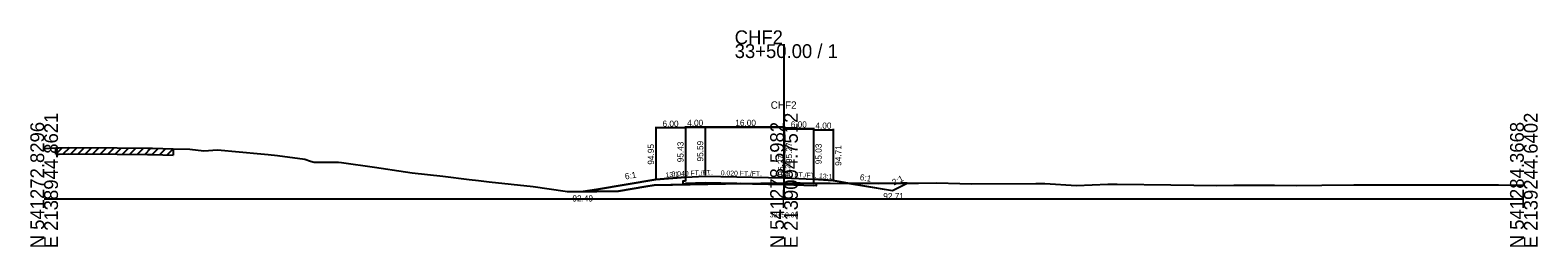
# Model space of a CAD drawing. Extents: x -12831 to 2303, y -10 to 39065.
# Drawn here: x 997.2 to 1302.8, y 6990.3 to 7034.2 of the extents above; entities that cross this region are included whole.
import ezdxf

# ---------------------------------------------------------------- set-up
doc = ezdxf.new("R2010")
doc.units = 0
for name, color, linetype in [('Level 5', 7, 'Continuous'), ('Level 53', 7, 'Continuous'), ('Level 54', 7, 'Continuous'), ('Level 55', 7, 'Continuous'), ('Level 7', 7, 'Continuous'), ('RD_GPK_XS_Cell', 7, 'Continuous'), ('RD_XS_EwShp', 7, 'Continuous'), ('RD_XS_ExGround', 7, 'Continuous'), ('RD_XS_ExPaveRet', 7, 'Continuous'), ('RD_XS_Pave', 7, 'Continuous'), ('RD_XS_TX_Baseline', 7, 'Continuous'), ('RD_XS_TX_Elev_EX', 7, 'Continuous'), ('RD_XS_TX_Elev_PR', 7, 'Continuous'), ('RD_XS_TX_Station', 7, 'Continuous')]:
    doc.layers.add(name, color=color, linetype=linetype)

msp = doc.modelspace()

# ---------------------------------------------------------------- linework, layer by layer
at = {"layer": 'Level 5'}
for p, q in [((1130, 7003.6), (1129.5, 7003.58)), ((1129.5, 7003.58), (1129.5, 7003.08)), ((1130, 7004.43), (1130, 7003.6)), ((1134, 7003.26), (1130, 7003.1)), ((1134, 7003.26), (1130, 7003.1)), ((1130, 7003.1), (1134, 7003.26)), ((1150, 7002.94), (1134, 7003.26)), ((1150, 7002.94), (1134, 7003.26)), ((1134, 7003.26), (1150, 7002.94)), ((1134, 7003.26), (1150, 7002.94)), ((1156, 7004.03), (1156, 7003.2)), ((1156, 7003.2), (1156.5, 7003.18)), ((1156.5, 7003.18), (1156.5, 7002.68)), ((1129.5, 7003.08), (1130, 7003.1)), ((1156, 7002.7), (1150, 7002.94)), ((1150, 7002.94), (1156, 7002.7)), ((1150, 7002.94), (1156, 7002.7)), ((1156.5, 7002.68), (1156, 7002.7))]:
    msp.add_line(p, q, dxfattribs=at)
at = {"layer": 'Level 54'}
for p, q in [((1124, 7014.58), (1124, 7004.15)), ((1130, 7014.38), (1124, 7014.38)), ((1130, 7014.74), (1130, 7004.63)), ((1130, 7014.74), (1130, 7004.63)), ((1130, 7014.74), (1130, 7004.63)), ((1130, 7014.58), (1130, 7004.63)), ((1130, 7014.54), (1134, 7014.54)), ((1130, 7014.54), (1134, 7014.54)), ((1134, 7014.54), (1130, 7014.54)), ((1134, 7014.74), (1134, 7004.79)), ((1134, 7014.74), (1134, 7004.79)), ((1134, 7014.74), (1134, 7004.79)), ((1134, 7014.74), (1134, 7004.79)), ((1134, 7014.74), (1134, 7004.79)), ((1134, 7014.74), (1134, 7004.79)), ((1134, 7014.74), (1134, 7004.79)), ((1134, 7014.54), (1150, 7014.54)), ((1134, 7014.54), (1150, 7014.54)), ((1150, 7014.54), (1134, 7014.54)), ((1150, 7014.54), (1134, 7014.54)), ((1150, 7014.74), (1150, 7004.47)), ((1150, 7014.74), (1150, 7004.47)), ((1150, 7014.74), (1150, 7004.47)), ((1150, 7014.74), (1150, 7004.47)), ((1150, 7014.42), (1150, 7004.47)), ((1150, 7014.42), (1150, 7004.47)), ((1150, 7014.42), (1150, 7004.47)), ((1150, 7014.22), (1156, 7014.22)), ((1156, 7014.22), (1150, 7014.22)), ((1156, 7014.22), (1150, 7014.22)), ((1156, 7014.42), (1156, 7004.23)), ((1156, 7014.42), (1156, 7004.23)), ((1156, 7014.42), (1156, 7004.23)), ((1156, 7014.18), (1156, 7004.23)), ((1156, 7013.98), (1160, 7013.98)), ((1160, 7014.18), (1160, 7003.91))]:
    msp.add_line(p, q, dxfattribs=at)
at = {"layer": 'Level 7'}
for p, q in [((1124, 7003.95), (1112, 7001.95)), ((1130, 7004.43), (1124, 7003.95)), ((1156, 7004.03), (1160, 7003.71)), ((1160, 7003.71), (1172, 7001.71)), ((1172, 7001.71), (1174.94, 7003.18)), ((1112, 7001.95), (1109.25, 7001.49))]:
    msp.add_line(p, q, dxfattribs=at)
at = {"layer": 'RD_GPK_XS_Cell'}
for p, q in [((1150, 7000), (1150, 7031.35)), ((1000, 7000), (1150, 7000)), ((1150, 7000), (1300, 7000))]:
    msp.add_line(p, q, dxfattribs=at)
at = {"layer": 'RD_XS_EwShp'}
for points in [[(1130, 7003.6), (1129.5, 7003.58), (1129.5, 7003.08), (1130, 7003.1), (1134, 7003.26), (1141.25, 7003.11), (1127.38, 7002.88), (1127.06, 7002.88), (1123.69, 7002.78), (1121.96, 7002.52), (1116.45, 7001.6), (1112.06, 7001.48), (1109.25, 7001.49), (1112, 7001.95), (1124, 7003.95), (1130, 7004.43)], [(1150, 7002.94), (1141.25, 7003.11), (1145.27, 7003.18), (1150, 7003.22), (1151.73, 7003.24), (1153.3, 7003.24), (1156, 7003.22), (1156, 7003.2), (1156.5, 7003.18), (1156.5, 7002.68), (1156, 7002.7)], [(1156, 7003.22), (1159.39, 7003.2), (1163.29, 7003.16), (1160, 7003.71), (1156, 7004.03)], [(1172, 7001.71), (1174.94, 7003.18), (1173.71, 7003.19), (1169.07, 7003.1), (1163.29, 7003.16)]]:
    msp.add_lwpolyline(points, close=True, dxfattribs=at)
at = {"layer": 'RD_XS_ExGround'}
for p, q in [((1000, 7010.23), (1001.03, 7010.28)), ((1001.03, 7010.28), (1002.38, 7010.37)), ((1002.38, 7010.37), (1003.07, 7010.39)), ((1003.07, 7010.39), (1005.01, 7010.45)), ((1005.01, 7010.45), (1014.78, 7010.37)), ((1014.78, 7010.37), (1020.93, 7010.32)), ((1020.93, 7010.32), (1021.96, 7010.28)), ((1021.96, 7010.28), (1026.18, 7010.17)), ((1026.18, 7010.17), (1029.55, 7010.11)), ((1029.55, 7010.11), (1032.37, 7009.76)), ((1032.37, 7009.76), (1035.11, 7009.97)), ((1035.11, 7009.97), (1043.94, 7009.16)), ((1043.94, 7009.16), (1045.44, 7009.02)), ((1045.44, 7009.02), (1047.34, 7008.83)), ((1047.34, 7008.83), (1052.88, 7008.06)), ((1052.88, 7008.06), (1054.01, 7007.66)), ((1054.01, 7007.66), (1054.75, 7007.46)), ((1054.75, 7007.46), (1059.7, 7007.45)), ((1059.7, 7007.45), (1060.29, 7007.38)), ((1060.29, 7007.38), (1066.95, 7006.45)), ((1066.95, 7006.45), (1073.23, 7005.48)), ((1073.23, 7005.48), (1074.61, 7005.31)), ((1074.61, 7005.31), (1080.86, 7004.63)), ((1080.86, 7004.63), (1086.17, 7003.95)), ((1086.17, 7003.95), (1088.05, 7003.71)), ((1088.05, 7003.71), (1090.19, 7003.45)), ((1090.19, 7003.45), (1099.12, 7002.52)), ((1127.38, 7002.88), (1145.27, 7003.18)), ((1145.27, 7003.18), (1150, 7003.22)), ((1150, 7003.22), (1151.73, 7003.24)), ((1151.73, 7003.24), (1153.3, 7003.24)), ((1153.3, 7003.24), (1159.39, 7003.2)), ((1159.39, 7003.2), (1169.07, 7003.1)), ((1169.07, 7003.1), (1173.71, 7003.19)), ((1173.71, 7003.19), (1177.3, 7003.17)), ((1177.3, 7003.17), (1180.97, 7003.28)), ((1180.97, 7003.28), (1185.63, 7003.13)), ((1099.12, 7002.52), (1105.63, 7001.55)), ((1105.63, 7001.55), (1106.03, 7001.5)), ((1106.03, 7001.5), (1112.06, 7001.48)), ((1112.06, 7001.48), (1116.45, 7001.6)), ((1116.45, 7001.6), (1121.96, 7002.52)), ((1121.96, 7002.52), (1123.69, 7002.78)), ((1123.69, 7002.78), (1127.06, 7002.88)), ((1127.06, 7002.88), (1127.38, 7002.88)), ((1185.63, 7003.13), (1188.01, 7003.05)), ((1188.01, 7003.05), (1201.04, 7003.16)), ((1201.04, 7003.16), (1202.86, 7003.11)), ((1202.86, 7003.11), (1209.3, 7002.73)), ((1209.3, 7002.73), (1215.65, 7002.99)), ((1215.65, 7002.99), (1217.58, 7003.02)), ((1217.58, 7003.02), (1228.43, 7002.86)), ((1228.43, 7002.86), (1237.77, 7002.76)), ((1237.77, 7002.76), (1241.21, 7002.77)), ((1241.21, 7002.77), (1249.45, 7002.77)), ((1249.45, 7002.77), (1253.99, 7002.76)), ((1253.99, 7002.76), (1259.07, 7002.82)), ((1259.07, 7002.82), (1265.52, 7002.85)), ((1265.52, 7002.85), (1273.53, 7002.85)), ((1273.53, 7002.85), (1279.56, 7002.88)), ((1279.56, 7002.88), (1281.22, 7002.86)), ((1281.22, 7002.86), (1292.34, 7002.83)), ((1292.34, 7002.83), (1294.83, 7002.85)), ((1294.83, 7002.85), (1297.94, 7002.82)), ((1297.94, 7002.82), (1300, 7002.81))]:
    msp.add_line(p, q, dxfattribs=at)
at = {"layer": 'RD_XS_ExPaveRet'}
for p, q in [((1002.38, 7009.07), (1003.72, 7010.41)), ((1002.38, 7009.07), (1002.38, 7010.37)), ((1003.88, 7009.11), (1005.21, 7010.45)), ((1005.38, 7009.15), (1006.67, 7010.44)), ((1006.88, 7009.13), (1008.17, 7010.42)), ((1008.38, 7009.12), (1009.67, 7010.41)), ((1009.88, 7009.11), (1011.17, 7010.4)), ((1011.38, 7009.1), (1012.67, 7010.39)), ((1012.88, 7009.09), (1014.17, 7010.38)), ((1014.38, 7009.07), (1015.67, 7010.36)), ((1015.88, 7009.06), (1017.17, 7010.35)), ((1017.38, 7009.05), (1018.67, 7010.34)), ((1018.88, 7009.03), (1020.17, 7010.32)), ((1020.38, 7009.02), (1021.65, 7010.29)), ((1021.88, 7008.99), (1023.14, 7010.25)), ((1023.38, 7008.94), (1024.64, 7010.21)), ((1024.88, 7008.9), (1026.14, 7010.17)), ((1026.18, 7010.17), (1026.18, 7008.87)), ((1002.38, 7009.07), (1003.07, 7009.09)), ((1003.07, 7009.09), (1005.01, 7009.15)), ((1005.01, 7009.15), (1014.78, 7009.07)), ((1014.78, 7009.07), (1020.93, 7009.02)), ((1020.93, 7009.02), (1021.96, 7008.98)), ((1021.96, 7008.98), (1026.18, 7008.87))]:
    msp.add_line(p, q, dxfattribs=at)
at = {"layer": 'RD_XS_Pave'}
for p, q in [((1130, 7004.43), (1134, 7004.59)), ((1134, 7004.59), (1150, 7004.27)), ((1150, 7004.27), (1156, 7004.03))]:
    msp.add_line(p, q, dxfattribs=at)

# ---------------------------------------------------------------- texts
at = {"layer": 'Level 53'}
for s, rotation, p in [('94.95', 90, (1123.63, 7006.95)), ('95.43', 90, (1129.63, 7007.43)), ('95.59', 90, (1133.63, 7007.59)), ('95.59', 90, (1133.63, 7007.59)), ('95.27', 90, (1151.63, 7007.27)), ('95.27', 90, (1151.63, 7007.27)), ('95.03', 90, (1157.63, 7007.03)), ('94.71', 90, (1161.63, 7006.71)), ('6:1', 9.4623, (1117.84, 7003.94)), ('6:1', 350.5377, (1165.3, 7003.84))]:
    msp.add_text(s, height=1.25, rotation=rotation, dxfattribs=at).set_placement(p)
for s, p in [('92.49', (1107.1, 6999.49)), ('92.71', (1170.13, 6999.96))]:
    msp.add_text(s, height=1.25, dxfattribs=at).set_placement(p)
at = {"layer": 'Level 54'}
for s, p in [('6.00', (1125.37, 7014.63)), ('4.00', (1130.37, 7014.79)), ('4.00', (1130.37, 7014.79)), ('4.00', (1130.37, 7014.79)), ('16.00', (1140.13, 7014.79)), ('16.00', (1140.13, 7014.79)), ('16.00', (1140.13, 7014.79)), ('16.00', (1140.13, 7014.79)), ('6.00', (1151.37, 7014.47)), ('6.00', (1151.37, 7014.47)), ('6.00', (1151.37, 7014.47)), ('4.00', (1156.37, 7014.23))]:
    msp.add_text(s, height=1.25, dxfattribs=at).set_placement(p)
at = {"layer": 'Level 55'}
for s, height, rotation, p in [('13:1', 1, 4.5739, (1126.03, 7004.36)), ('0.040 FT./FT.', 1, 2.2906, (1127.22, 7004.57)), ('0.040 FT./FT.', 1, 2.2906, (1127.22, 7004.57)), ('0.040 FT./FT.', 1, 2.2906, (1127.22, 7004.57)), ('0.020 FT./FT.', 1, 358.8542, (1137.18, 7004.78)), ('0.020 FT./FT.', 1, 358.8542, (1137.18, 7004.78)), ('0.020 FT./FT.', 1, 358.8542, (1137.18, 7004.78)), ('0.020 FT./FT.', 1, 358.8542, (1137.18, 7004.78)), ('0.040 FT./FT.', 1, 357.7094, (1148.24, 7004.59)), ('0.040 FT./FT.', 1, 357.7094, (1148.24, 7004.59)), ('0.040 FT./FT.', 1, 357.7094, (1148.24, 7004.59)), ('13:1', 1, 355.4261, (1157.07, 7004.2)), ('2:1', 1.25, 26.5651, (1172.29, 7002.7))]:
    msp.add_text(s, height=height, rotation=rotation, dxfattribs=at).set_placement(p)
at = {"layer": 'RD_GPK_XS_Cell'}
for s, p in [('CHF2', (1140, 7031.35)), ('33+50.00 / 1', (1140, 7028.55))]:
    msp.add_text(s, height=2.8, dxfattribs=at).set_placement(p)
for s, p in [('N 541272.8296', (1000, 6990)), ('E 2138944.8621', (1002.8, 6990)), ('N 541278.5982', (1150, 6990)), ('E 2139094.7512', (1152.8, 6990)), ('N 541284.3668', (1300, 6990)), ('E 2139244.6402', (1302.8, 6990))]:
    msp.add_text(s, height=2.8, rotation=90, dxfattribs=at).set_placement(p)
at = {"layer": 'RD_XS_TX_Baseline'}
msp.add_text('CHF2', height=1.5, dxfattribs=at).set_placement((1147.31, 7018.27))
at = {"layer": 'RD_XS_TX_Elev_EX'}
msp.add_text('94.22', height=1, rotation=90, dxfattribs=at).set_placement((1151.25, 7004.22))
at = {"layer": 'RD_XS_TX_Elev_PR'}
msp.add_text(' 95.27', height=1.25, rotation=90, dxfattribs=at).set_placement((1150, 7004.27))
at = {"layer": 'RD_XS_TX_Station'}
msp.add_text('33+50.00', height=1, dxfattribs=at).set_placement((1147.1, 6996.27))

doc.saveas('drawing.dxf')
